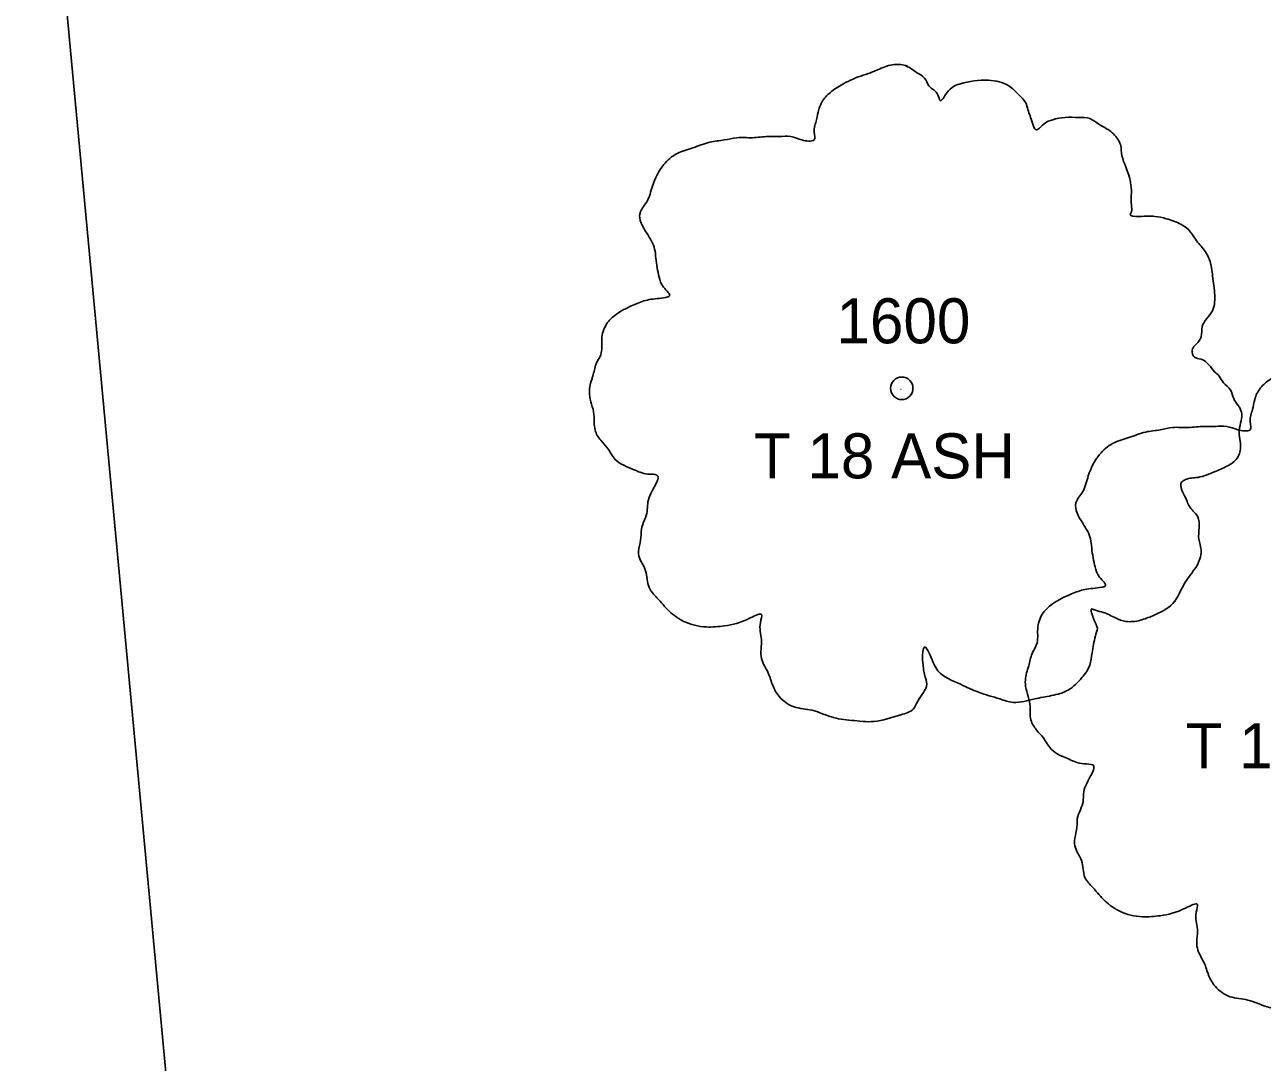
# Model space of a CAD drawing. Extents: x 1965304 to 1970247, y 1117014 to 1118201.
# Drawn here: x 1966593.43 to 1966620.94, y 1117434.58 to 1117457.62 of the extents above; entities that cross this region are included whole.
import ezdxf

# ---------------------------------------------------------------- set-up
doc = ezdxf.new("R2010")
doc.units = 0
doc.layers.add('RD_EX_VEG', color=7, linetype='Continuous')
doc.layers.add('RD_EX_VEG_txCode', color=7, linetype='Continuous')

msp = doc.modelspace()

# ---------------------------------------------------------------- linework, layer by layer
at = {"layer": 'RD_EX_VEG'}
msp.add_line((1966597.045, 1117429.245), (1966593.432, 1117467.989), dxfattribs=at)
for centre, radius in [((1966612.923, 1117449.547), 0.25), ((1966612.923, 1117449.547), 0.25), ((1966612.91, 1117449.528), 0.0001), ((1966612.91, 1117449.528), 0.0001)]:
    msp.add_circle(centre, radius, dxfattribs=at)
for points in [[(1966613.054, 1117456.715), (1966612.755, 1117456.74), (1966612.43, 1117456.64), (1966612.18, 1117456.54), (1966611.955, 1117456.465), (1966611.73, 1117456.365), (1966611.43, 1117456.19), (1966611.205, 1117455.99), (1966611.08, 1117455.74), (1966611.03, 1117455.515), (1966610.98, 1117455.24), (1966610.98, 1117455.065), (1966610.855, 1117455.04), (1966610.705, 1117455.065), (1966610.456, 1117455.14), (1966610.206, 1117455.14), (1966609.956, 1117455.14), (1966609.606, 1117455.115), (1966609.256, 1117455.115), (1966608.981, 1117455.065), (1966608.656, 1117455.015), (1966608.282, 1117454.89), (1966607.932, 1117454.765), (1966607.632, 1117454.515), (1966607.382, 1117454.041), (1966607.257, 1117453.691), (1966607.107, 1117453.441), (1966607.257, 1117452.991), (1966607.432, 1117452.641), (1966607.457, 1117452.441), (1966607.532, 1117452.017), (1966607.632, 1117451.792), (1966607.757, 1117451.592), (1966607.682, 1117451.567), (1966607.307, 1117451.517), (1966607.007, 1117451.417), (1966606.582, 1117451.192), (1966606.357, 1117450.967), (1966606.257, 1117450.642), (1966606.232, 1117450.292), (1966606.133, 1117450.092), (1966606.058, 1117449.818), (1966606.033, 1117449.743), (1966605.983, 1117449.418), (1966606.083, 1117448.968), (1966606.108, 1117448.618), (1966606.232, 1117448.393), (1966606.382, 1117448.218), (1966606.557, 1117447.968), (1966606.957, 1117447.743), (1966607.282, 1117447.643), (1966607.482, 1117447.619), (1966607.307, 1117447.119), (1966607.257, 1117446.769), (1966607.132, 1117446.369), (1966607.132, 1117446.294), (1966607.082, 1117445.819), (1966607.232, 1117445.494), (1966607.307, 1117445.12), (1966607.482, 1117444.895), (1966607.757, 1117444.595), (1966608.082, 1117444.37), (1966608.581, 1117444.245), (1966608.981, 1117444.27), (1966609.556, 1117444.445), (1966609.806, 1117444.52), (1966609.781, 1117444.345), (1966609.806, 1117443.97), (1966609.806, 1117443.545), (1966609.956, 1117443.22), (1966610.056, 1117442.946), (1966610.206, 1117442.696), (1966610.531, 1117442.471), (1966610.93, 1117442.396), (1966611.355, 1117442.246), (1966611.805, 1117442.171), (1966612.305, 1117442.146), (1966612.905, 1117442.296), (1966613.179, 1117442.421), (1966613.279, 1117442.596), (1966613.479, 1117442.971), (1966613.429, 1117443.195), (1966613.454, 1117443.795), (1966613.554, 1117443.62), (1966613.729, 1117443.27), (1966614.229, 1117442.971), (1966614.629, 1117442.796), (1966615.104, 1117442.646), (1966615.403, 1117442.571), (1966615.878, 1117442.646), (1966616.253, 1117442.721), (1966616.628, 1117442.846), (1966616.928, 1117443.12), (1966617.103, 1117443.395), (1966617.153, 1117443.67), (1966617.228, 1117444.045), (1966617.278, 1117444.22)], [(1966613.054, 1117456.715), (1966612.755, 1117456.74), (1966612.43, 1117456.64), (1966612.18, 1117456.54), (1966611.955, 1117456.465), (1966611.73, 1117456.365), (1966611.43, 1117456.19), (1966611.205, 1117455.99), (1966611.08, 1117455.74), (1966611.03, 1117455.515), (1966610.98, 1117455.24), (1966610.98, 1117455.065), (1966610.855, 1117455.04), (1966610.705, 1117455.065), (1966610.456, 1117455.14), (1966610.206, 1117455.14), (1966609.956, 1117455.14), (1966609.606, 1117455.115), (1966609.256, 1117455.115), (1966608.981, 1117455.065), (1966608.656, 1117455.015), (1966608.282, 1117454.89), (1966607.932, 1117454.765), (1966607.632, 1117454.515), (1966607.382, 1117454.041), (1966607.257, 1117453.691), (1966607.107, 1117453.441), (1966607.257, 1117452.991), (1966607.432, 1117452.641), (1966607.457, 1117452.441), (1966607.532, 1117452.017), (1966607.632, 1117451.792), (1966607.757, 1117451.592), (1966607.682, 1117451.567), (1966607.307, 1117451.517), (1966607.007, 1117451.417), (1966606.582, 1117451.192), (1966606.357, 1117450.967), (1966606.257, 1117450.642), (1966606.232, 1117450.292), (1966606.133, 1117450.092), (1966606.058, 1117449.818), (1966606.033, 1117449.743), (1966605.983, 1117449.418), (1966606.083, 1117448.968), (1966606.108, 1117448.618), (1966606.232, 1117448.393), (1966606.382, 1117448.218), (1966606.557, 1117447.968), (1966606.957, 1117447.743), (1966607.282, 1117447.643), (1966607.482, 1117447.619), (1966607.307, 1117447.119), (1966607.257, 1117446.769), (1966607.132, 1117446.369), (1966607.132, 1117446.294), (1966607.082, 1117445.819), (1966607.232, 1117445.494), (1966607.307, 1117445.12), (1966607.482, 1117444.895), (1966607.757, 1117444.595), (1966608.082, 1117444.37), (1966608.581, 1117444.245), (1966608.981, 1117444.27), (1966609.556, 1117444.445), (1966609.806, 1117444.52), (1966609.781, 1117444.345), (1966609.806, 1117443.97), (1966609.806, 1117443.545), (1966609.956, 1117443.22), (1966610.056, 1117442.946), (1966610.206, 1117442.696), (1966610.531, 1117442.471), (1966610.93, 1117442.396), (1966611.355, 1117442.246), (1966611.805, 1117442.171), (1966612.305, 1117442.146), (1966612.905, 1117442.296), (1966613.179, 1117442.421), (1966613.279, 1117442.596), (1966613.479, 1117442.971), (1966613.429, 1117443.195), (1966613.454, 1117443.795), (1966613.554, 1117443.62), (1966613.729, 1117443.27), (1966614.229, 1117442.971), (1966614.629, 1117442.796), (1966615.104, 1117442.646), (1966615.403, 1117442.571), (1966615.878, 1117442.646), (1966616.253, 1117442.721), (1966616.628, 1117442.846), (1966616.928, 1117443.12), (1966617.103, 1117443.395), (1966617.153, 1117443.67), (1966617.228, 1117444.045), (1966617.278, 1117444.22)], [(1966617.278, 1117444.22), (1966617.203, 1117444.395), (1966617.153, 1117444.645), (1966617.228, 1117444.62), (1966617.403, 1117444.57), (1966617.677, 1117444.445), (1966617.902, 1117444.37), (1966618.227, 1117444.395), (1966618.502, 1117444.495), (1966618.952, 1117444.77), (1966619.227, 1117445.245), (1966619.502, 1117445.644), (1966619.577, 1117445.969), (1966619.527, 1117446.194), (1966619.502, 1117446.694), (1966619.302, 1117446.944), (1966619.252, 1117447.069), (1966619.152, 1117447.469), (1966619.227, 1117447.519), (1966619.502, 1117447.569), (1966619.876, 1117447.693), (1966620.151, 1117447.818), (1966620.376, 1117447.993), (1966620.451, 1117448.218), (1966620.426, 1117448.618), (1966620.476, 1117449.018), (1966620.401, 1117449.168), (1966620.301, 1117449.318), (1966620.226, 1117449.518), (1966620.076, 1117449.668), (1966619.976, 1117449.818), (1966619.876, 1117449.917), (1966619.752, 1117450.067), (1966619.577, 1117450.192), (1966619.427, 1117450.242), (1966619.377, 1117450.392), (1966619.527, 1117450.592), (1966619.577, 1117450.692), (1966619.602, 1117450.917), (1966619.827, 1117451.267), (1966619.876, 1117451.667), (1966619.827, 1117452.092), (1966619.777, 1117452.366), (1966619.627, 1117452.641), (1966619.427, 1117452.891), (1966619.302, 1117453.066), (1966619.127, 1117453.191), (1966618.802, 1117453.316), (1966618.552, 1117453.366), (1966618.202, 1117453.366), (1966618.002, 1117453.416), (1966618.027, 1117453.466), (1966618.027, 1117453.616), (1966618.027, 1117453.891), (1966617.952, 1117454.341), (1966617.802, 1117454.84), (1966617.802, 1117454.865), (1966617.702, 1117455.115), (1966617.478, 1117455.315), (1966617.303, 1117455.415), (1966617.103, 1117455.54), (1966616.853, 1117455.565), (1966616.553, 1117455.565), (1966616.278, 1117455.515), (1966616.078, 1117455.415), (1966615.903, 1117455.29), (1966615.828, 1117455.44), (1966615.728, 1117455.74), (1966615.678, 1117455.89), (1966615.528, 1117456.065), (1966615.304, 1117456.265), (1966614.854, 1117456.39), (1966614.229, 1117456.315), (1966613.929, 1117456.115), (1966613.779, 1117455.94), (1966613.729, 1117456.065), (1966613.529, 1117456.265), (1966613.429, 1117456.44), (1966613.254, 1117456.565), (1966613.104, 1117456.665), (1966613.004, 1117456.715)], [(1966617.278, 1117444.22), (1966617.203, 1117444.395), (1966617.153, 1117444.645), (1966617.228, 1117444.62), (1966617.403, 1117444.57), (1966617.677, 1117444.445), (1966617.902, 1117444.37), (1966618.227, 1117444.395), (1966618.502, 1117444.495), (1966618.952, 1117444.77), (1966619.227, 1117445.245), (1966619.502, 1117445.644), (1966619.577, 1117445.969), (1966619.527, 1117446.194), (1966619.502, 1117446.694), (1966619.302, 1117446.944), (1966619.252, 1117447.069), (1966619.152, 1117447.469), (1966619.227, 1117447.519), (1966619.502, 1117447.569), (1966619.876, 1117447.693), (1966620.151, 1117447.818), (1966620.376, 1117447.993), (1966620.451, 1117448.218), (1966620.426, 1117448.618), (1966620.476, 1117449.018), (1966620.401, 1117449.168), (1966620.301, 1117449.318), (1966620.226, 1117449.518), (1966620.076, 1117449.668), (1966619.976, 1117449.818), (1966619.876, 1117449.917), (1966619.752, 1117450.067), (1966619.577, 1117450.192), (1966619.427, 1117450.242), (1966619.377, 1117450.392), (1966619.527, 1117450.592), (1966619.577, 1117450.692), (1966619.602, 1117450.917), (1966619.827, 1117451.267), (1966619.876, 1117451.667), (1966619.827, 1117452.092), (1966619.777, 1117452.366), (1966619.627, 1117452.641), (1966619.427, 1117452.891), (1966619.302, 1117453.066), (1966619.127, 1117453.191), (1966618.802, 1117453.316), (1966618.552, 1117453.366), (1966618.202, 1117453.366), (1966618.002, 1117453.416), (1966618.027, 1117453.466), (1966618.027, 1117453.616), (1966618.027, 1117453.891), (1966617.952, 1117454.341), (1966617.802, 1117454.84), (1966617.802, 1117454.865), (1966617.702, 1117455.115), (1966617.478, 1117455.315), (1966617.303, 1117455.415), (1966617.103, 1117455.54), (1966616.853, 1117455.565), (1966616.553, 1117455.565), (1966616.278, 1117455.515), (1966616.078, 1117455.415), (1966615.903, 1117455.29), (1966615.828, 1117455.44), (1966615.728, 1117455.74), (1966615.678, 1117455.89), (1966615.528, 1117456.065), (1966615.304, 1117456.265), (1966614.854, 1117456.39), (1966614.229, 1117456.315), (1966613.929, 1117456.115), (1966613.779, 1117455.94), (1966613.729, 1117456.065), (1966613.529, 1117456.265), (1966613.429, 1117456.44), (1966613.254, 1117456.565), (1966613.104, 1117456.665), (1966613.004, 1117456.715)], [(1966622.743, 1117450.276), (1966622.443, 1117450.301), (1966622.118, 1117450.201), (1966621.868, 1117450.101), (1966621.643, 1117450.026), (1966621.418, 1117449.926), (1966621.118, 1117449.751), (1966620.893, 1117449.551), (1966620.768, 1117449.301), (1966620.718, 1117449.076), (1966620.669, 1117448.801), (1966620.669, 1117448.626), (1966620.544, 1117448.601), (1966620.394, 1117448.626), (1966620.144, 1117448.701), (1966619.894, 1117448.701), (1966619.644, 1117448.701), (1966619.294, 1117448.676), (1966618.944, 1117448.676), (1966618.669, 1117448.626), (1966618.345, 1117448.576), (1966617.97, 1117448.451), (1966617.62, 1117448.326), (1966617.32, 1117448.077), (1966617.07, 1117447.602), (1966616.945, 1117447.252), (1966616.795, 1117447.002), (1966616.945, 1117446.552), (1966617.12, 1117446.202), (1966617.145, 1117446.002), (1966617.22, 1117445.578), (1966617.32, 1117445.353), (1966617.445, 1117445.153), (1966617.37, 1117445.128), (1966616.995, 1117445.078), (1966616.695, 1117444.978), (1966616.27, 1117444.753), (1966616.046, 1117444.528), (1966615.946, 1117444.203), (1966615.921, 1117443.853), (1966615.821, 1117443.654), (1966615.746, 1117443.379), (1966615.721, 1117443.304), (1966615.671, 1117442.979), (1966615.771, 1117442.529), (1966615.796, 1117442.179), (1966615.921, 1117441.954), (1966616.071, 1117441.779), (1966616.245, 1117441.529), (1966616.645, 1117441.305), (1966616.97, 1117441.205), (1966617.17, 1117441.18), (1966616.995, 1117440.68), (1966616.945, 1117440.33), (1966616.82, 1117439.93), (1966616.82, 1117439.855), (1966616.77, 1117439.38), (1966616.92, 1117439.055), (1966616.995, 1117438.681), (1966617.17, 1117438.456), (1966617.445, 1117438.156), (1966617.77, 1117437.931), (1966618.27, 1117437.806), (1966618.669, 1117437.831), (1966619.244, 1117438.006), (1966619.494, 1117438.081), (1966619.469, 1117437.906), (1966619.494, 1117437.531), (1966619.494, 1117437.106), (1966619.644, 1117436.782), (1966619.744, 1117436.507), (1966619.894, 1117436.257), (1966620.219, 1117436.032), (1966620.619, 1117435.957), (1966621.043, 1117435.807), (1966621.493, 1117435.732), (1966621.993, 1117435.707), (1966622.593, 1117435.857), (1966622.868, 1117435.982), (1966622.968, 1117436.157), (1966623.167, 1117436.532), (1966623.117, 1117436.757), (1966623.142, 1117437.356), (1966623.242, 1117437.181), (1966623.417, 1117436.831), (1966623.917, 1117436.532), (1966624.317, 1117436.357), (1966624.792, 1117436.207), (1966625.092, 1117436.132), (1966625.566, 1117436.207), (1966625.941, 1117436.282), (1966626.316, 1117436.407), (1966626.616, 1117436.682), (1966626.791, 1117436.956), (1966626.841, 1117437.231), (1966626.916, 1117437.606), (1966626.966, 1117437.781)], [(1966622.743, 1117450.276), (1966622.443, 1117450.301), (1966622.118, 1117450.201), (1966621.868, 1117450.101), (1966621.643, 1117450.026), (1966621.418, 1117449.926), (1966621.118, 1117449.751), (1966620.893, 1117449.551), (1966620.768, 1117449.301), (1966620.718, 1117449.076), (1966620.669, 1117448.801), (1966620.669, 1117448.626), (1966620.544, 1117448.601), (1966620.394, 1117448.626), (1966620.144, 1117448.701), (1966619.894, 1117448.701), (1966619.644, 1117448.701), (1966619.294, 1117448.676), (1966618.944, 1117448.676), (1966618.669, 1117448.626), (1966618.345, 1117448.576), (1966617.97, 1117448.451), (1966617.62, 1117448.326), (1966617.32, 1117448.077), (1966617.07, 1117447.602), (1966616.945, 1117447.252), (1966616.795, 1117447.002), (1966616.945, 1117446.552), (1966617.12, 1117446.202), (1966617.145, 1117446.002), (1966617.22, 1117445.578), (1966617.32, 1117445.353), (1966617.445, 1117445.153), (1966617.37, 1117445.128), (1966616.995, 1117445.078), (1966616.695, 1117444.978), (1966616.27, 1117444.753), (1966616.046, 1117444.528), (1966615.946, 1117444.203), (1966615.921, 1117443.853), (1966615.821, 1117443.654), (1966615.746, 1117443.379), (1966615.721, 1117443.304), (1966615.671, 1117442.979), (1966615.771, 1117442.529), (1966615.796, 1117442.179), (1966615.921, 1117441.954), (1966616.071, 1117441.779), (1966616.245, 1117441.529), (1966616.645, 1117441.305), (1966616.97, 1117441.205), (1966617.17, 1117441.18), (1966616.995, 1117440.68), (1966616.945, 1117440.33), (1966616.82, 1117439.93), (1966616.82, 1117439.855), (1966616.77, 1117439.38), (1966616.92, 1117439.055), (1966616.995, 1117438.681), (1966617.17, 1117438.456), (1966617.445, 1117438.156), (1966617.77, 1117437.931), (1966618.27, 1117437.806), (1966618.669, 1117437.831), (1966619.244, 1117438.006), (1966619.494, 1117438.081), (1966619.469, 1117437.906), (1966619.494, 1117437.531), (1966619.494, 1117437.106), (1966619.644, 1117436.782), (1966619.744, 1117436.507), (1966619.894, 1117436.257), (1966620.219, 1117436.032), (1966620.619, 1117435.957), (1966621.043, 1117435.807), (1966621.493, 1117435.732), (1966621.993, 1117435.707), (1966622.593, 1117435.857), (1966622.868, 1117435.982), (1966622.968, 1117436.157), (1966623.167, 1117436.532), (1966623.117, 1117436.757), (1966623.142, 1117437.356), (1966623.242, 1117437.181), (1966623.417, 1117436.831), (1966623.917, 1117436.532), (1966624.317, 1117436.357), (1966624.792, 1117436.207), (1966625.092, 1117436.132), (1966625.566, 1117436.207), (1966625.941, 1117436.282), (1966626.316, 1117436.407), (1966626.616, 1117436.682), (1966626.791, 1117436.956), (1966626.841, 1117437.231), (1966626.916, 1117437.606), (1966626.966, 1117437.781)]]:
    msp.add_spline(points, degree=3, dxfattribs=at)

# ---------------------------------------------------------------- texts
at = {"layer": 'RD_EX_VEG_txCode'}
for s, p in [('1600', (1966611.474, 1117450.547)), ('1600', (1966611.474, 1117450.547)), ('T 18 ASH', (1966609.639, 1117447.547)), ('T 18 ASH', (1966609.639, 1117447.547)), ('T 10 OAK', (1966619.233, 1117441.108)), ('T 10 OAK', (1966619.233, 1117441.108))]:
    msp.add_text(s, height=1, dxfattribs=at).set_placement(p)

doc.saveas('drawing.dxf')
